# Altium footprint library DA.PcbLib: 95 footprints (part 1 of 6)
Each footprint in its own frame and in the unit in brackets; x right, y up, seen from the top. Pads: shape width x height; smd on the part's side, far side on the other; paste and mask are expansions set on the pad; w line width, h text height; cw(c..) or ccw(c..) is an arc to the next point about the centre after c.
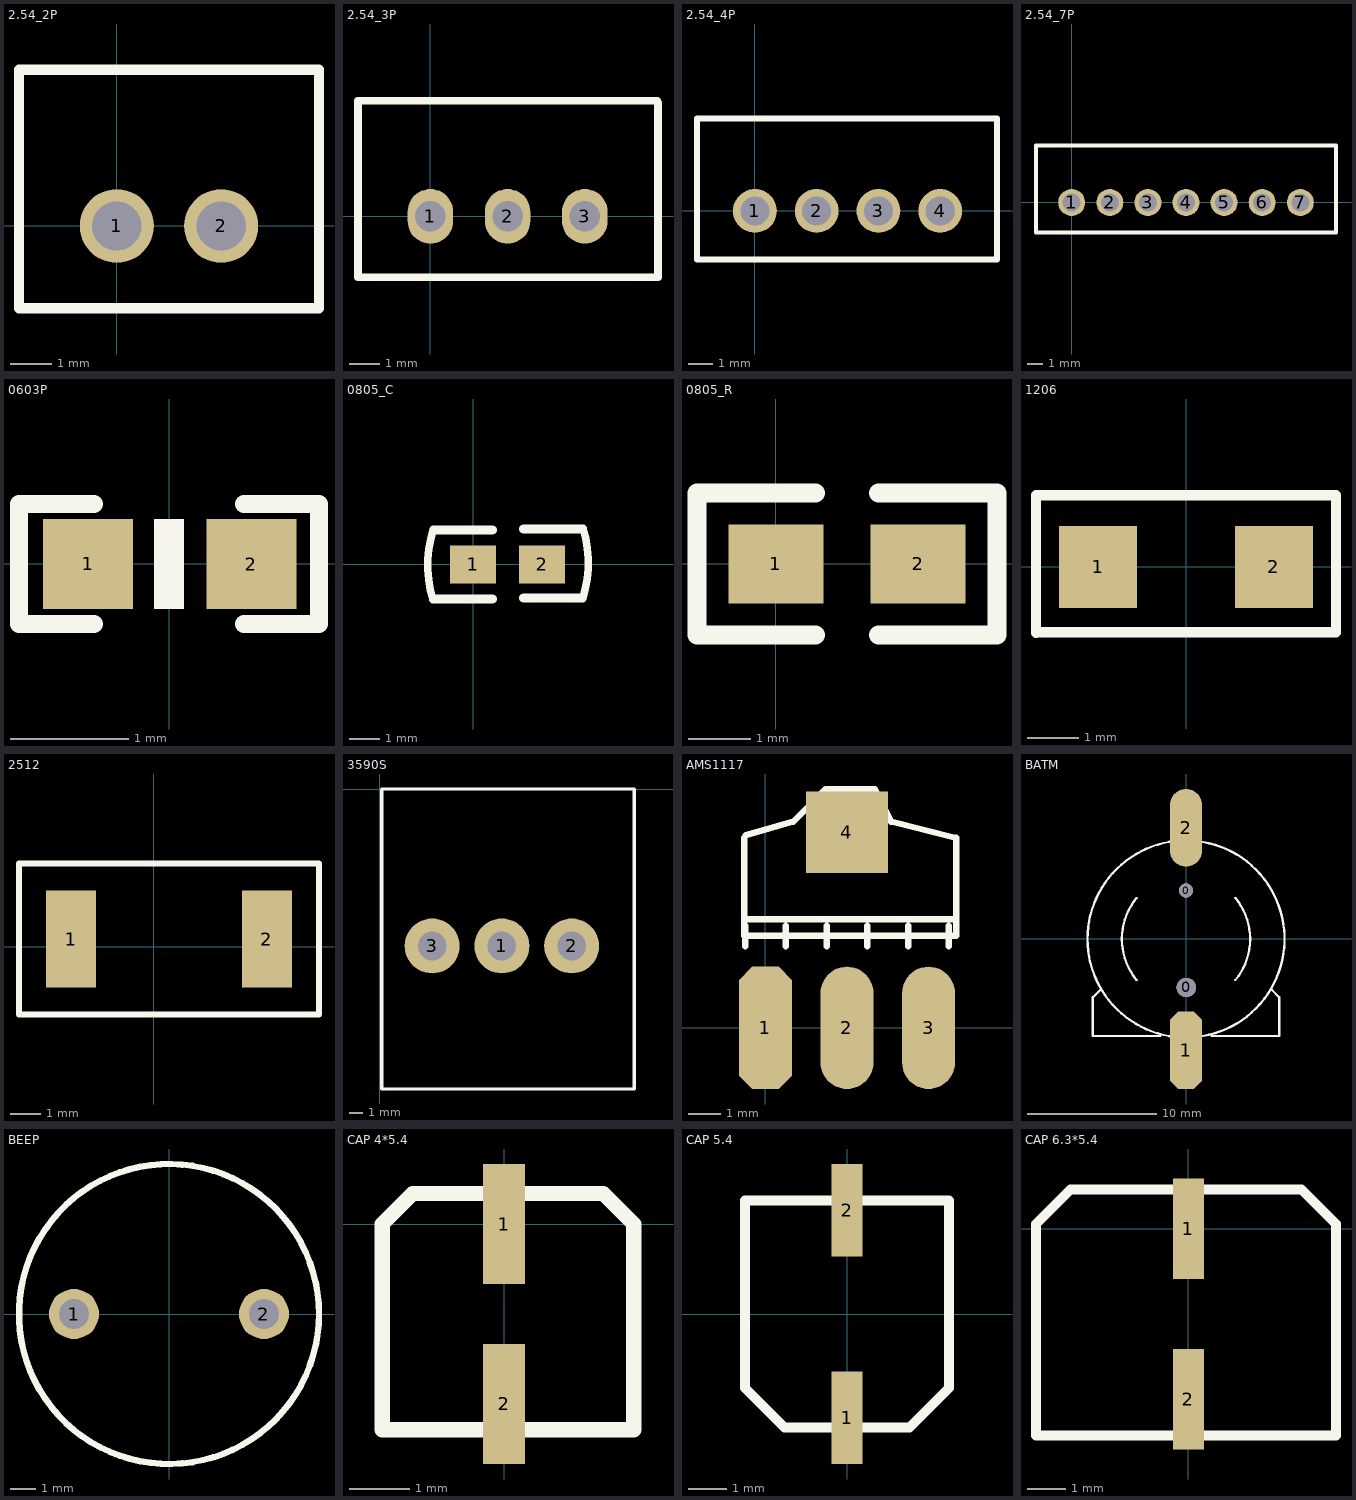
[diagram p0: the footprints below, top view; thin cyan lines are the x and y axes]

## 2.54_2P [mm]
pads (2):
  round 1.8 hole 1.2: 1(0,0) 2(2.54,0)
Top Overlay:
  lines w0.254: -2.38,-2 -2.38,3.8 4.92,3.8 4.92,-2 -2.38,-2

## 2.54_3P [mm]
pads (3):
  oval 1.5x1.8 hole 1: 1(0,0) 2(2.54,0) 3(5.08,0)
Top Overlay:
  lines w0.254: 7.46,-2 -2.38,-2 -2.38,3.8 7.46,3.8 ; 7.485,-2 7.485,3.737

## 2.54_4P [mm]
pads (4):
  round 1.8 hole 1.2: 1(0,0) 2(2.54,0) 3(5.08,0) 4(7.62,0)
Top Overlay:
  lines w0.254: -2.38,-2 9.957,-2 9.957,3.8 -2.38,3.8 -2.38,-2

## 2.54_7P [mm]
pads (7):
  round 1.8 hole 1.2: 1(0,0) 2(2.54,0) 3(5.08,0) 4(7.62,0) 5(10.16,0) 6(12.7,0) 7(15.24,0)
Top Overlay:
  lines w0.254: -2.38,-2 17.62,-2 17.62,3.8 -2.38,3.8 -2.38,-2

## 0603P [mil]
pads (2):
  rect 30x30 smd: 1(-27,0) 2(27.5,-0.06)
Top Overlay:
  region: 5,-15.06 5,14.94 -5,14.94 -5,-15.06
  lines w6: -25,-20.06 -50,-20.06 -50,19.94 -25,19.94 ; 25,-20.06 50,-20.06 50,19.94 25,19.94

## 0805_C [mil]
pads (2):
  rect 60x50 smd: 1(0,-0.06) 2(90,-0.06)
Top Overlay:
  lines w10: -52.43,-45.82 cw(c91,-1) -51.88,45.55 ; 142.88,-44.55 ccw(c0,2) 143.43,46.82
  lines w12: -50,-45.06 25,-45.06 ; -50,44.94 25,44.94 ; 66,-43.94 141,-43.94 ; 66,46.06 141,46.06

## 0805_R [mil]
pads (2):
  rect 60x50 smd: 1(0,-0.06) 2(90,-0.06)
Top Overlay:
  lines w12: 25,-45.06 -50,-45.06 -50,44.94 25,44.94 ; 65,-45.06 140,-45.06 140,44.94 65,44.94

## 1206 [mm]
pads (2):
  rect 1.52x1.6 smd: 1(-1.71,0) 2(1.71,0)
Top Overlay:
  lines w0.2: -2.921,-1.282 -2.921,1.397 2.921,1.397 2.921,-1.27 -2.921,-1.27

## 2512 [mm]
pads (2):
  rect 1.65x3.2 smd: 1(-2.732,0.254) 2(3.748,0.254)
Top Overlay:
  lines w0.2: -4.457,-2.246 -4.457,0.254 -4.457,2.754 5.473,2.754 5.473,-2.246 -4.457,-2.246

## 3590S [mm]
pads (3):
  round 4 hole 2.08: 1(8.89,-11.43) 2(13.97,-11.43) 3(3.81,-11.43)
Top Overlay:
  lines w0.254: 0.127,-0.127 0.127,-21.844 18.542,-21.844 18.542,0 0.127,0

## AMS1117 [mil]
height 149.61
pads (4):
  oct 65x150 smd: 1(0.03,-0.06)
  oval 65x150 smd: 2(100.03,-0.06) 3(200.03,-0.06)
  rect 100x100 smd: 4(100.03,239.94)
Top Overlay:
  lines w7.87: -25.97,232.94 -25.97,132.94 ; -24.97,99.94 -24.97,124.94 ; -24.3,236.27 34.03,252.94 74.03,292.94 134.03,292.94 154.03,252.94 234.03,232.94 234.03,112.94 ; 25.03,99.94 25.03,124.94 ; 75.03,99.94 75.03,124.94 ; 125.03,99.94 125.03,124.94 ; 175.03,99.94 175.03,124.94 ; 225.03,99.94 225.03,124.94 ; -25.97,132.94 234.03,132.94 234.03,112.94 ; -25.97,132.94 -25.97,112.94 234.03,112.94

## BATM [mm]
pads (4):
  round 1.1 hole 1.1 unplated: 0(0,3.748)
  round 1.5 hole 1.5 unplated: 0(0.025,-3.752)
  oct 2.5x6 smd: 1(0,-8.602)
  oval 2.5x6 smd: 2(0,8.598)
Top Overlay:
  lines w0.178: -6.6,-3.902 -7.2,-4.502 -7.2,-7.502 -2,-7.502 ; -3.815,-3.171 cw(c0,-0.002) -3.812,3.171 ; -0.833,-7.576 cw(c0,-0.002) -7.62,-0.002 cw(c0,-0.002) -0.833,7.573 ; 0.833,-7.576 ccw(c0,-0.002) 0.833,7.573 ; 2,-7.502 7.2,-7.502 7.2,-4.502 6.625,-3.927 ; 3.81,-3.177 ccw(c0,-0.002) 3.812,3.171

## BEEP [mm]
pads (2):
  round 2 hole 1.2: 1(-3.8,0) 2(3.8,0)
Top Overlay:
  circle w0.254: c0,0 r6

## CAP 4*5.4 [mm]
pads (2):
  rect 0.7x2 smd: 1(0,0) 2(0,-3)
Top Overlay:
  lines w0.254: -2.032,-3.429 -2.032,0 -1.524,0.508 1.651,0.508 2.159,0 2.159,-3.429 -2.032,-3.429

## CAP 5.4 [mm]
pads (2):
  rect 0.8x2.4 smd: 1(0,-2.7) 2(0,2.7)
Top Overlay:
  lines w0.254: -2.65,-1.922 -1.622,-2.95 1.622,-2.95 2.65,-1.922 2.65,2.95 -2.65,2.95 -2.65,-1.922

## CAP 6.3*5.4 [mm]
pads (2):
  rect 0.8x2.6 smd: 1(0,0) 2(0,-4.4)
Top Overlay:
  lines w0.254: -3.937,-5.334 -3.937,0.127 -3.048,1.016 2.921,1.016 3.81,0.127 3.81,-5.334 -3.937,-5.334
